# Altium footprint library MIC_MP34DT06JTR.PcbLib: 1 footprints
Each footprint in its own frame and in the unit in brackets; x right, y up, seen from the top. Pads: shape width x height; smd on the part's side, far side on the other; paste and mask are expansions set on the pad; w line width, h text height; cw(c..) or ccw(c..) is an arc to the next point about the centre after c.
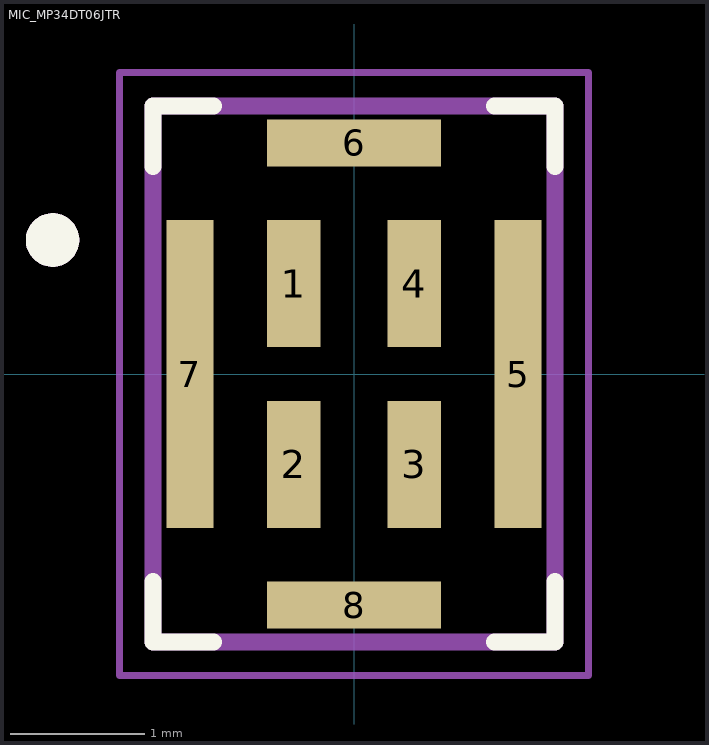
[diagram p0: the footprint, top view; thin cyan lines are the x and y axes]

## MIC_MP34DT06JTR [mm]
pads (8):
  rect 0.4x0.95 smd: 1(-0.45,0.675) 2(-0.45,-0.675) 3(0.45,-0.675) 4(0.45,0.675)
  rect 0.35x2.3 smd: 5(1.225,0) 7(-1.225,0)
  rect 1.3x0.35 smd: 6(0,1.725) 8(0,-1.725)
Top Overlay:
  circle w0.2: c-2.25,1 r0.1
  lines w0.127: -1.5,-1.55 -1.5,-2 -1.05,-2 ; -1.5,1.55 -1.5,2 -1.05,2 ; 1.05,-2 1.5,-2 1.5,-1.55 ; 1.05,2 1.5,2 1.5,1.55
Mechanical 13:
  circle w0.2: c-2.25,1 r0.1
  lines w0.127: -1.5,-2 -1.5,2 1.5,2 1.5,-2 -1.5,-2
Mechanical 15:
  lines w0.05: -1.75,-2.25 1.75,-2.25 1.75,2.25 -1.75,2.25 -1.75,-2.25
